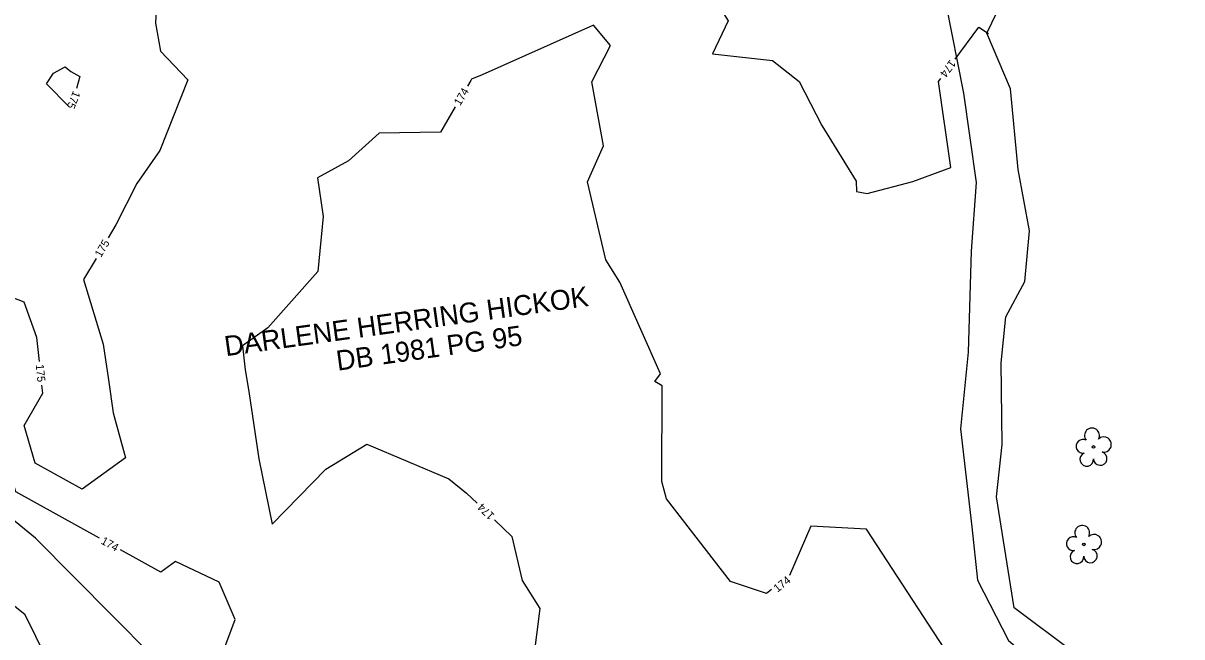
# Model space of a CAD drawing. Extents: x 2086416 to 2115205, y 575507 to 632762.
# Drawn here: x 2111776.5 to 2112066, y 581467.3 to 581620.8 of the extents above; entities that cross this region are included whole.
import ezdxf

# ---------------------------------------------------------------- set-up
doc = ezdxf.new("R2010")
doc.units = 0
for name, color, linetype in [('DTM Contours Major', 7, 'Continuous'), ('DTM Contours Major Text', 7, 'Continuous'), ('DTM Contours Minor', 7, 'Continuous'), ('DTM Contours Minor Text', 7, 'Continuous'), ('Exist Hydro Stream or Body of Water', 7, 'Continuous'), ('Exist Property Deed Book Text', 7, 'Continuous'), ('Exist Property Owner Text', 7, 'Continuous'), ('Exist Vegetation Tree CELL', 7, 'Continuous'), ('Exist Vegetation Woods Line', 7, 'Continuous')]:
    doc.layers.add(name, color=color, linetype=linetype)

# ---------------------------------------------------------------- blocks, each defined once
blk = doc.blocks.new('EXIST VEGETATION TREE')
at = {"layer": 'Exist Vegetation Tree CELL'}
blk.add_line((0, 0), (0, 0), dxfattribs=at)
blk.add_circle((0, 0), 0.00652, dxfattribs=at)
for centre, radius, start, end in [((-0.0077, 0.0575), 0.0371, 330.16508, 219.71335), ((-0.0521, 0.0031), 0.0345, 62.66361, 279.3457), ((0.051, 0.0118), 0.038, 257.1011, 134.19993), ((-0.0341, -0.0624), 0.0338, 111.56708, 6.23104), ((0.0335, -0.058), 0.034, 181.28216, 74.55999)]:
    blk.add_arc(centre, radius, start, end, dxfattribs=at)

msp = doc.modelspace()

# ---------------------------------------------------------------- linework, layer by layer
at = {"layer": 'DTM Contours Major'}
for points in [[(2111820.07, 581645.83), (2111817.92, 581646.44), (2111808.25, 581646.5), (2111811.2, 581641.49), (2111810.29, 581636.32), (2111809.51, 581620.82), (2111810.8, 581613.76), (2111817.65, 581606.62), (2111810.63, 581588.91), (2111804.83, 581580.65), (2111799.65, 581570.34), (2111797.73, 581567.1)], [(2111782.3, 581605.61), (2111784.01, 581608.29), (2111786.99, 581609.88), (2111788.36, 581608.71), (2111790.62, 581607.48), (2111789.82, 581604.42)], [(2111780.53, 581536.2), (2111779.91, 581542.21), (2111776.72, 581551.05), (2111767.61, 581554.53), (2111746.99, 581573.66), (2111745.59, 581575.02), (2111748.2, 581578.53), (2111769.31, 581602.49), (2111766.72, 581604.09), (2111762.55, 581607.47)], [(2111787.98, 581599.85), (2111782.3, 581605.61)], [(2111794.67, 581561.93), (2111791.54, 581556.65), (2111796.48, 581540.55), (2111797.78, 581531.62), (2111798.98, 581523.31), (2111802.05, 581512.09), (2111791.22, 581504.22), (2111779.44, 581510.73), (2111776.74, 581520.15), (2111781.34, 581528.23), (2111781.14, 581530.23)]]:
    msp.add_lwpolyline(points, dxfattribs=at)
at = {"layer": 'DTM Contours Minor'}
for points in [[(2112001.57, 581666.12), (2111965.52, 581661.61), (2111964.4, 581661.24), (2111963.9, 581661.19), (2111958.38, 581660.11), (2111945.74, 581643.25), (2111945.53, 581632.64), (2111952.64, 581621.35), (2111948.73, 581613.13), (2111963.74, 581611.46), (2111970.42, 581606.19), (2111976.09, 581595.16), (2111984.65, 581581.25), (2111984.7, 581578.65), (2111987.39, 581578.17), (2111998.82, 581581.21), (2112008.29, 581584.73), (2112005.23, 581606.22), (2112005.78, 581606.97)], [(2111963.5, 581479.12), (2111962.2, 581478.15), (2111953.21, 581481.17), (2111937.2, 581501.82), (2111936.07, 581506.16), (2111936.16, 581530.08), (2111934.34, 581531.17), (2111935.7, 581533.07), (2111925.59, 581555.99), (2111922.09, 581561.58), (2111917.53, 581581.13), (2111921.47, 581590.14), (2111918.62, 581606.14), (2111923.22, 581615.22), (2111918.98, 581620.26), (2111891.19, 581607.9), (2111888.52, 581606.78), (2111888.34, 581606.47), (2111887.5, 581605.04)], [(2112009.35, 581611.79), (2112015.27, 581619.77), (2112017.74, 581618.23)], [(2111884.45, 581599.87), (2111880.73, 581593.56), (2111865.45, 581593.25), (2111857.75, 581586.36), (2111850.01, 581582.13), (2111851.41, 581572.47), (2111850.12, 581558.71), (2111837.61, 581544.61), (2111831.26, 581540.08), (2111831.96, 581534.09), (2111832.86, 581528.7), (2111835.36, 581511.87), (2111838.72, 581495.5), (2111852.1, 581509.28), (2111862.32, 581515.47), (2111882.86, 581506.83), (2111887.27, 581503.23), (2111889.92, 581500.71)], [(2111795.57, 581491.95), (2111774.6, 581503.54), (2111772.79, 581509.85), (2111742.06, 581525.95)], [(2111894.26, 581496.57), (2111898.61, 581492.43), (2111901.19, 581481.43), (2111905.56, 581474.44), (2111901.59, 581442.83), (2111895.67, 581435.72), (2111904.81, 581432.38)], [(2111936.8, 581431.38), (2111937.22, 581432.68), (2111937.59, 581431.38), (2112017, 581428.25), (2112026.43, 581428.02), (2112017.76, 581430.28), (2112017.05, 581436.29), (2112012.18, 581454.89), (2112012.09, 581456.17), (2112011.8, 581456.57), (2111987.24, 581494.26), (2111973.35, 581495.02), (2111968.01, 581482.65)], [(2111808.47, 581449.49), (2111823.16, 581455.94), (2111824.76, 581459.12), (2111829.42, 581471.68), (2111825.46, 581480.96), (2111814.57, 581486.18), (2111810.87, 581483.49), (2111800.82, 581489.04)]]:
    msp.add_lwpolyline(points, dxfattribs=at)
at = {"layer": 'Exist Hydro Stream or Body of Water'}
for points in [[(2112026.79, 581556.19), (2112027.99, 581568.85), (2112025.16, 581584.18), (2112023.21, 581604.37), (2112017.27, 581618.27), (2112027.13, 581638.7)], [(2111785.01, 581456.38), (2111776.98, 581472.85), (2111753.02, 581492.1), (2111736.76, 581510.47), (2111717.38, 581521.12), (2111676.84, 581560.27), (2111646, 581586.7)], [(2112067.22, 581424.64), (2112074.1, 581427.73), (2112073.39, 581436.72), (2112064.5, 581445.16), (2112053.96, 581452.19), (2112024.09, 581474.58), (2112019.7, 581502.3), (2112021.09, 581515.42), (2112020.9, 581535.88), (2112022.05, 581547.38), (2112026.79, 581556.19)]]:
    msp.add_lwpolyline(points, dxfattribs=at)
at = {"layer": 'Exist Vegetation Woods Line'}
for points in [[(2112016.22, 581659.52), (2112010.15, 581640.89), (2112007.07, 581625.66), (2112011.47, 581603.31), (2112014.66, 581580.91), (2112013.34, 581563.73), (2112012.63, 581538.51), (2112010.71, 581519.35), (2112013.56, 581494.84), (2112014.97, 581481.49), (2112022.73, 581466.4), (2112037.51, 581453.75), (2112050.78, 581446.7), (2112062.82, 581439.28), (2112065.18, 581428.19)], [(2111779.57, 581491.97), (2111763.79, 581504.85), (2111745.34, 581525.06), (2111717.3, 581555.59), (2111690.35, 581575.95), (2111665.09, 581587.14), (2111644.35, 581594.34), (2111622.46, 581605.4), (2111614.18, 581617.92), (2111615.41, 581630.25), (2111644.69, 581636.02), (2111711.67, 581643.9), (2111763.23, 581655.57), (2111785.51, 581656)], [(2111823.9, 581373.12), (2111830.89, 581408.91), (2111827.79, 581443.34), (2111779.57, 581491.97)]]:
    msp.add_lwpolyline(points, dxfattribs=at)

# ---------------------------------------------------------------- block references
at = {"layer": 'Exist Vegetation Tree CELL', "xscale": 50, "yscale": 50}
for p in [(2112043.96, 581514.81), (2112041.52, 581490.44)]:
    msp.add_blockref('EXIST VEGETATION TREE', p, dxfattribs=at)

# ---------------------------------------------------------------- texts
at = {"layer": 'DTM Contours Major Text'}
for rotation, p in [(248.061, (2111788.99, 581604)), (59.348, (2111795.9, 581562.05)), (275.8302, (2111779.61, 581535.38))]:
    msp.add_text('175', height=2, rotation=rotation, dxfattribs=at).set_placement(p)
at = {"layer": 'DTM Contours Minor Text'}
for rotation, p in [(233.437, (2112008.12, 581611.8)), (59.4515, (2111885.68, 581599.99)), (136.3685, (2111894.42, 581497.8)), (331.0641, (2111795.72, 581490.72)), (38.149, (2111964.96, 581478.35))]:
    msp.add_text('174', height=2, rotation=rotation, dxfattribs=at).set_placement(p)
at = {"layer": 'Exist Property Deed Book Text'}
msp.add_text('DB 1981 PG 95', height=5, rotation=7.8831, dxfattribs=at).set_placement((2111855.06, 581533.86))
at = {"layer": 'Exist Property Owner Text'}
msp.add_text('DARLENE HERRING HICKOK', height=5, rotation=7.883, dxfattribs=at).set_placement((2111827.12, 581537.49))

doc.saveas('drawing.dxf')
